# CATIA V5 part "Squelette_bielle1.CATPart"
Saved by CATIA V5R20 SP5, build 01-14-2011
Part number: Squelette_bielle1
Publications: "Droite.2", "Point.2", "Point.1", "Droite.1", "Droite.3", "Plan.1"
Bounding box of the stored display mesh (mm): x -10 to 10, y 0 to 8, z 0 to 0
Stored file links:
  F:\PROJ IAO\CATIA\Squelette_bielle1.CATPart
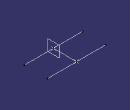
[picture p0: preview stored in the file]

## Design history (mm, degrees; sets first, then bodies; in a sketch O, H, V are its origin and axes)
Set1
  Plane1: type Offset, RefPlane yz-plane, Offset 0
  Point1: (0, 0, 0)
  Line1: type Normal, RefPoint Point1, RefSkin Plane1, Start -10, End 10
  Point2: (0, 8, 0)
  Line2: type PtDir, RefPoint Point2, Direction Plane1, Start -10, End 10
  Line3: type PtPt, FirstPoint Point2, SecondPoint Point1
Body1 (main body)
